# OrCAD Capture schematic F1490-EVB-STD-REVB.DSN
size Custom; title: F1490 EVB STD REVB; rev: A
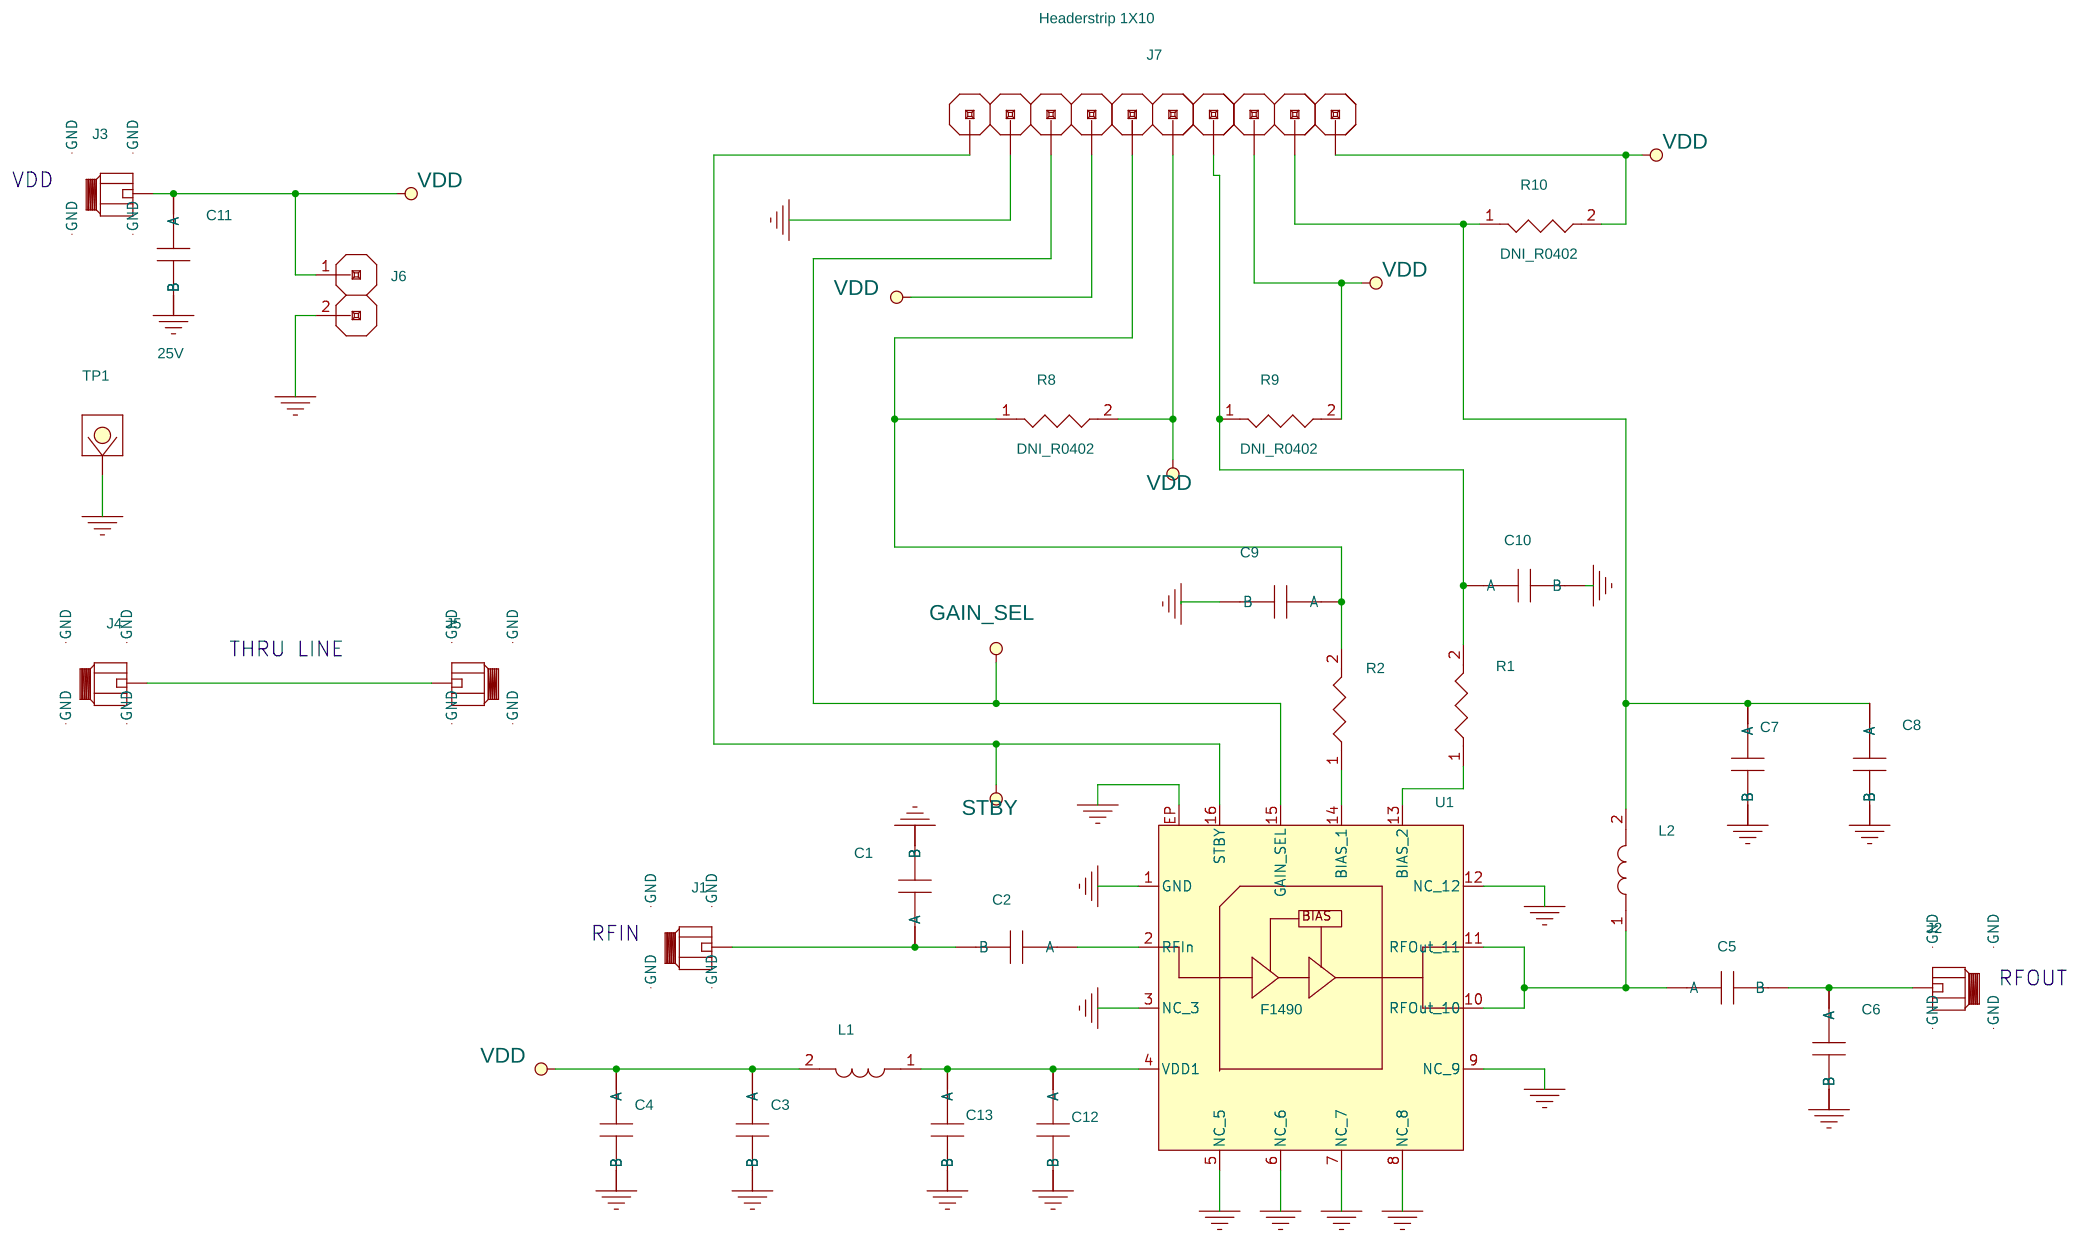
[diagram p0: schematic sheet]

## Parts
C1  0.8pF  [CAPC1005N]
C2  10pF  [CAPC1005N]
C3  33pF  [CAPC1005N]
C4  33pF  [CAPC1005N]
C5  22pF  [CAPC1005N]
C6  0.7pF  [CAPC1005N]
C7  33pF  [CAPC1005N]
C8  0.1uF  [CAPC1608N]
C9  33pF  [CAPC1005N]
C10  33pF  [CAPC1005N]
C11  1uF  [CAPC1608N]
C12  2pF  [CAPC0603N]
C13  2pF  [CAPC0603N]
J1  Cinch_142_0701_851  [SMA_JACK_END_LAUNCH_375]
J2  Cinch_142_0701_851  [SMA_JACK_END_LAUNCH_375]
J3  Cinch_142_0701_851  [SMA_JACK_END_LAUNCH_375]
J4  Cinch_142_0701_851  [SMA_JACK_END_LAUNCH_375]
J5  Cinch_142_0701_851  [SMA_JACK_END_LAUNCH_375]
J6  DNI Headerstrip 1X2  [HEADER_1X2_VERTICAL]
J7  Headerstrip 1X10  [HEADER_1X10_VERTICAL]
L1  1.5nH  [INDC1005N]
L2  1.8nH  [INDC1005N]
R1  1.50K  [RESC1005N]
R2  1.00K  [RESC1005N]
R8  DNI_R0402  [RESC1005N]
R9  DNI_R0402  [RESC1005N]
R10  DNI_R0402  [RESC1005N]
TP1  Loop  [TP254_102]
U1  F1490  [QFN-16_EP160]

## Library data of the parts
C1 = CAP_1005N: Pack Type: 0402; Part Number: GJM1555C1HR80BB01D; Rating: 50V
C2 = CAP_1005N: Pack Type: 0402; Part Number: GJM1555C1H100JB01D; Rating: 50V
C3 C4 C7 C9 C10 = CAP_1005N: Pack Type: 0402; Part Number: GRM1555C1E330J; Rating: 25V
C5 = CAP_1005N: Pack Type: 0402; Part Number: C0402C220J3GAC; Rating: 25V
C6 = CAP_1005N: Pack Type: 0402; Part Number: GJM1555C1HR70BB01D; Rating: 50V
C8 = CAP_1608N: Pack Type: 0603; Part Number: C0603C104K5R; Rating: 50V
C11 = CAP_1608N: Pack Type: 0603; Part Number: GRM188R61E105K; Rating: 25V
C12 C13 = CAP_0603N: Pack Type: 0201; Part Number: GRM0335C1H2R0B; Rating: 50V
J1-J5 = SMA_EDGE: Pack Type: EDGE_STR; Part Number: 142_0701_851; Rating: 50 OHM
J6 = HEADER_1X2: Pack Type: Vertical; Part Number: DNI 1x2; Rating: TBD
J7 = HEADER_1X10: Pack Type: Vertical; Part Number: 0022284103; Rating: Male, 100mil Pitch
L1 = IND_1005N: Pack Type: 0402; Part Number: LQG15HN1N5S02D; Rating: 1A, 100mOhm
L2 = IND_1005N: Pack Type: 0402; Part Number: LQG15HS1N8C02D; Rating: 950mA, 80mOhm
R1 = RESISTOR_1005N: Pack Type: 0402; Part Number: CRCW04021K50FK; Rating: 1/16W
R2 = RESISTOR_1005N: Pack Type: 0402; Part Number: RC0402JR-071KL; Rating: 1/16W
R8-R10 = RESISTOR_1005N: Pack Type: 0402
TP1 = TESTPOINT: Pack Type: Thru Hole; Part Number: 5001; Rating: Black
U1 = F1490: Pack Type: QFN16

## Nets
GND: C1.2(B) C3.2(B) C4.2(B) C6.2(B) C7.2(B) C8.2(B) C9.2(B) C10.2(B) C11.2(B) C12.2(B) C13.2(B) J1.2(GND) J1.3(GND) J1.4(GND) J1.5(GND) J2.2(GND) J2.3(GND) J2.4(GND) J2.5(GND) J3.2(GND) J3.3(GND) J3.4(GND) J3.5(GND) J4.2(GND) J4.3(GND) J4.4(GND) J4.5(GND) J5.2(GND) J5.3(GND) J5.4(GND) J5.5(GND) J6.2 J7.2 TP1.1 U1.1(GND) U1.3(NC) U1.5(NC) U1.6(NC) U1.7(NC) U1.8(NC) U1.9(NC) U1.12(NC) U1.EP
VDD: C3.1(A) C4.1(A) C11.1(A) J3.1 J6.1 J7.4 J7.6 J7.8 J7.10 L1.2(B) R8.2 R9.2 R10.2
GAIN_SEL: J7.3 U1.15(GAIN_SEL)
STBY: J7.1 U1.16(STBY)
N963622: C5.1(A) L2.1(A) U1.10(RFOut) U1.11(RFOut)
N973158: J4.1 J5.1
N977718: C1.1(A) C2.2(B) J1.1
N995247: C12.1(A) C13.1(A) L1.1(A) U1.4(VDD1)
N996909: C7.1(A) C8.1(A) J7.9 L2.2(B) R10.1
N1050153: C2.1(A) U1.2(RFIn)
N1050802: C5.2(B) C6.1(A) J2.1
N1055643: C10.1(A) J7.7 R1.2 R9.1
N1055675: R2.1 U1.14(BIAS_1)
N1058474: C9.1(A) J7.5 R2.2 R8.1
N1082898: R1.1 U1.13(BIAS_2)

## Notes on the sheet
- VDD
- THRU LINE
- RFIN
- RFOUT
